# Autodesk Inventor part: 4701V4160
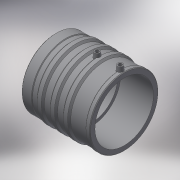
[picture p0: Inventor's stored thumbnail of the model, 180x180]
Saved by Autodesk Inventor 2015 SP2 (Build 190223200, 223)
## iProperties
Created: 2017-08
Part Number: 4701V4160
Material: Generic
Description: PLASSON PVC TO PE ADAPTOR 160
Document SubType Name: Modeling
Designer: Кирилл
Density: 1 g/cm^3
Appearance: Default
Author: Кирилл
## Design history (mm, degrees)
derived "4701V4.ipt"
feature "Solid1::4701V4.ipt"
tag "TaggingFeature1"
body "Solid1"
other parameters: "d0" = 187, "d2" = 77, "d4" = 193, "d5" = 45 deg, "d6" = 45 deg, "d7" = 184, "d8" = 187.21, "d9" = 26.95, "d10" = 144, "d11" = 152, "d12" = 12.6, "d13" = 54, "d15" = 9.24, "d16" = 9.24, "d18" = 106, "d19" = 15, "d20" = 15, "d22" = 4 deg, "d23" = 4, "d24" = 4, "d27" = 14, "d28" = 0, "d29" = 4, "d30" = 0, "L_" = 187, "L_2" = 77, "D_" = 193, "A_" = 106
